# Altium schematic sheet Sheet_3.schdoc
size 250 x 192 mm
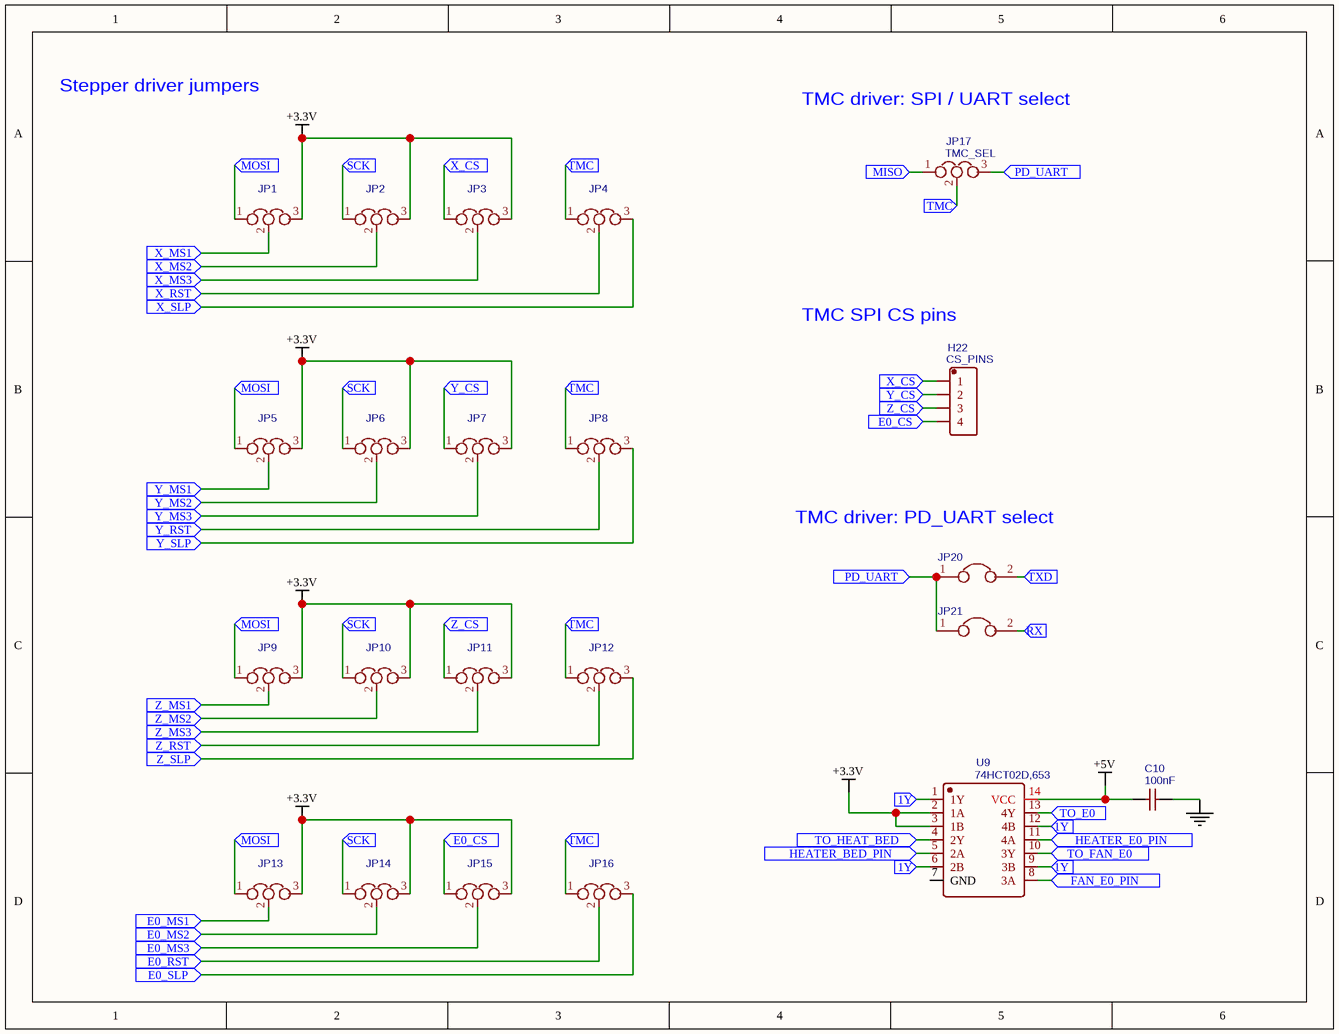
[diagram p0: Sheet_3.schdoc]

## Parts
C10  100nF  [0805]
H22  CS_PINS  [DIP-1X4P-2.54MM-M]
JP1  JP_X_MS1  [HDR-3X1/2.54]  (value not drawn)
JP2  JP_X_MS2  [HDR-3X1/2.54]  (value not drawn)
JP3  JP_X_MS3  [HDR-3X1/2.54]  (value not drawn)
JP4  JP_X_RST  [HDR-3X1/2.54]  (value not drawn)
JP5  JP_Y_MS1  [HDR-3X1/2.54]  (value not drawn)
JP6  JP_Y_MS2  [HDR-3X1/2.54]  (value not drawn)
JP7  JP_Y_MS3  [HDR-3X1/2.54]  (value not drawn)
JP8  JP_Y_RST  [HDR-3X1/2.54]  (value not drawn)
JP9  JP_Z_MS1  [HDR-3X1/2.54]  (value not drawn)
JP10  JP_Z_MS2  [HDR-3X1/2.54]  (value not drawn)
JP11  JP_Z_MS3  [HDR-3X1/2.54]  (value not drawn)
JP12  JP_Z_RST  [HDR-3X1/2.54]  (value not drawn)
JP13  JP_E0_MS1  [HDR-3X1/2.54]  (value not drawn)
JP14  JP_E0_MS2  [HDR-3X1/2.54]  (value not drawn)
JP15  JP_E0_MS3  [HDR-3X1/2.54]  (value not drawn)
JP16  JP_E0_RST  [HDR-3X1/2.54]  (value not drawn)
JP17  TMC_SEL  [HDR-3X1/2.54]
JP20  PD_UART_TX  [HDR-2X1/2.54]  (value not drawn)
JP21  PD_UART_RX  [HDR-2X1/2.54]  (value not drawn)
U9  74HCT02D,653  [SOIC-14_150MIL]

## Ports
1Y, E0_CS, E0_MS1, E0_MS2, E0_MS3, E0_RST, E0_SLP, FAN_E0_PIN, HEATER_BED_PIN, HEATER_E0_PIN, MISO, MOSI, PD_UART, RX, SCK, TMC, TO_E0, TO_FAN_E0, TO_HEAT_BED, TXD, X_CS, X_MS1, X_MS2, X_MS3, X_RST, X_SLP, Y_CS, Y_MS1, Y_MS2, Y_MS3, Y_RST, Y_SLP, Z_CS, Z_MS1, Z_MS2, Z_MS3, Z_RST, Z_SLP

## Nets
+3.3V: JP1.3 JP2.3 JP3.3 JP5.3 JP6.3 JP7.3 JP9.3 JP10.3 JP11.3 JP13.3 JP14.3 JP15.3 U9.2(1A) U9.3(1B)
+5V: C10.1 U9.14(VCC)
GND: C10.2
1Y: U9.1(1Y) U9.6(2B) U9.9(3B) U9.12(4B) ; port 1Y
E0_CS: H22.4 JP15.1 ; port E0_CS
E0_MS1: JP13.2 ; port E0_MS1
E0_MS2: JP14.2 ; port E0_MS2
E0_MS3: JP15.2 ; port E0_MS3
E0_RST: JP16.2 ; port E0_RST
E0_SLP: JP16.3 ; port E0_SLP
FAN_E0_PIN: U9.8(3A) ; port FAN_E0_PIN
HEATER_BED_PIN: U9.5(2A) ; port HEATER_BED_PIN
HEATER_E0_PIN: U9.11(4A) ; port HEATER_E0_PIN
MISO: JP17.1 ; port MISO
MOSI: JP1.1 JP5.1 JP9.1 JP13.1 ; port MOSI
PD_UART: JP17.3 JP20.1 JP21.1 ; port PD_UART
RX: JP21.2 ; port RX
SCK: JP2.1 JP6.1 JP10.1 JP14.1 ; port SCK
TMC: JP4.1 JP8.1 JP12.1 JP16.1 JP17.2 ; port TMC
TO_E0: U9.13(4Y) ; port TO_E0
TO_FAN_E0: U9.10(3Y) ; port TO_FAN_E0
TO_HEAT_BED: U9.4(2Y) ; port TO_HEAT_BED
TXD: JP20.2 ; port TXD
X_CS: H22.1 JP3.1 ; port X_CS
X_MS1: JP1.2 ; port X_MS1
X_MS2: JP2.2 ; port X_MS2
X_MS3: JP3.2 ; port X_MS3
X_RST: JP4.2 ; port X_RST
X_SLP: JP4.3 ; port X_SLP
Y_CS: H22.2 JP7.1 ; port Y_CS
Y_MS1: JP5.2 ; port Y_MS1
Y_MS2: JP6.2 ; port Y_MS2
Y_MS3: JP7.2 ; port Y_MS3
Y_RST: JP8.2 ; port Y_RST
Y_SLP: JP8.3 ; port Y_SLP
Z_CS: H22.3 JP11.1 ; port Z_CS
Z_MS1: JP9.2 ; port Z_MS1
Z_MS2: JP10.2 ; port Z_MS2
Z_MS3: JP11.2 ; port Z_MS3
Z_RST: JP12.2 ; port Z_RST
Z_SLP: JP12.3 ; port Z_SLP

Not connected (* = marked no-connect by the designer): U9 7(GND)

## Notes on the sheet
- Stepper driver jumpers
- TMC driver: SPI / UART select
- TMC SPI CS pins
- (near JP20) TMC driver: PD_UART select

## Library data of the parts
C10 = (no symbol name): BOM_Manufacturer: YAGEO; BOM_Manufacturer Part: CC0805JRX7R9BB104; nameAlias: Capacitance
H22 = (no symbol name): BOM_Manufacturer: Ckmtw; BOM_Manufacturer Part: 210S-1*4P L=11.6MMGold-plated black; Contributor: LCSC
JP1-JP17 JP20 JP21 = (no symbol name): Contributor: KiCad
U9 = (no symbol name): BOM_Manufacturer: Nexperia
